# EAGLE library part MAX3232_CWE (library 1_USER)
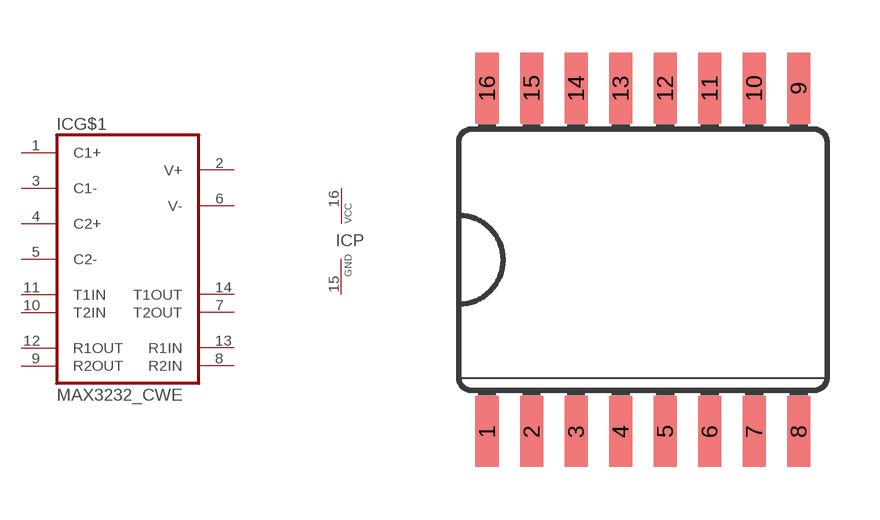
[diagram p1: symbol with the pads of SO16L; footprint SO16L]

Designator prefix IC; gates P=VCC_GND G$1=MAX3232

## MAX3232_CWE  [SO16L]
1  G$1:C1+  pas
2  G$1:V+  pas
3  G$1:C1-  pas
4  G$1:C2+  pas
5  G$1:C2-  pas
6  G$1:V-  pas
7  G$1:T2OUT  out
8  G$1:R2IN  in
9  G$1:R2OUT  out
10  G$1:T2IN  in
11  G$1:T1IN  in
12  G$1:R1OUT  out
13  G$1:R1IN  in
14  G$1:T1OUT  out
15  P:GND  pwr
16  P:VCC  pwr

## Footprint SO16L (pad centres in mm)
smd 0.66 x 2.032: 1 -4.445,-4.902; 2 -3.175,-4.902; 3 -1.905,-4.902; 4 -0.635,-4.902; 5 0.635,-4.902; 6 1.905,-4.902; 7 3.175,-4.902; 8 4.445,-4.902; 9 4.445,4.902; 10 3.175,4.902; 11 1.905,4.902; 12 0.635,4.902; 13 -0.635,4.902; 14 -1.905,4.902; 15 -3.175,4.902; 16 -4.445,4.902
